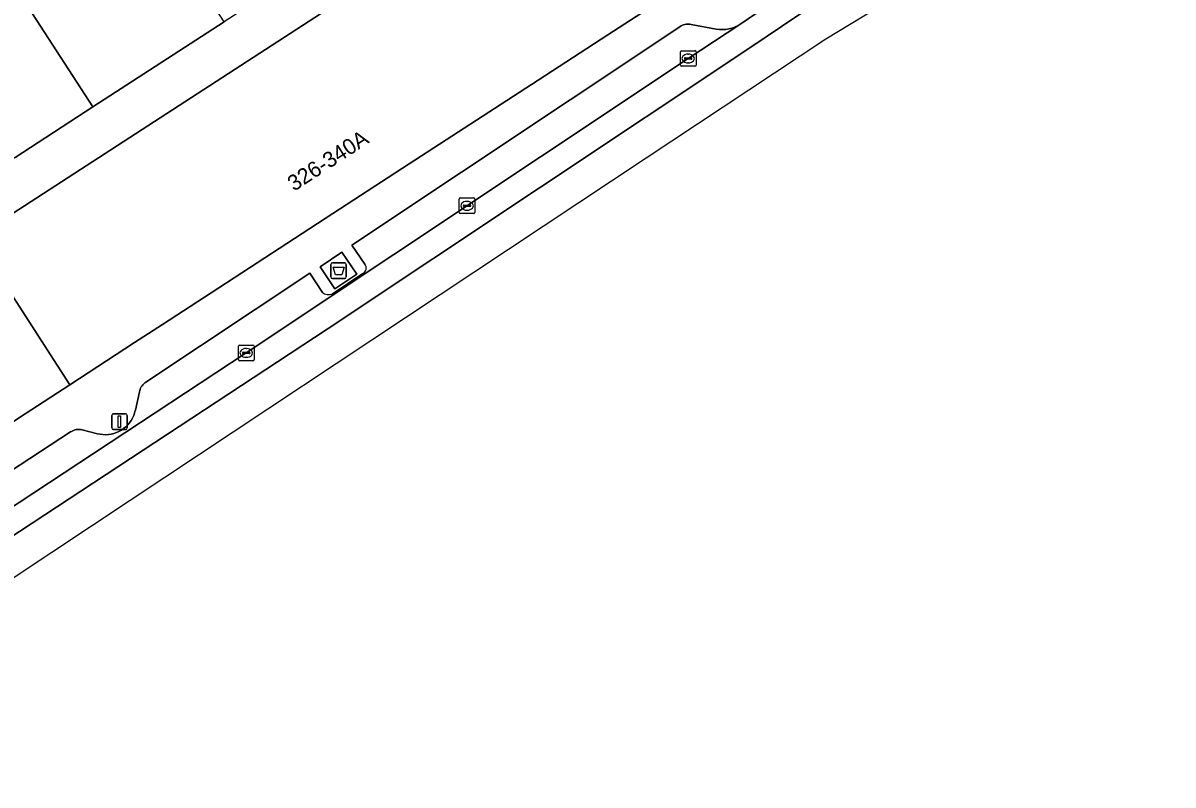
# Model space of a CAD drawing. Extents: x 159217 to 160349, y 381246 to 382172.
# Drawn here: x 160088.8 to 160162.3, y 381567.9 to 381616.5 of the extents above; entities that cross this region are included whole.
import ezdxf

# ---------------------------------------------------------------- set-up
doc = ezdxf.new("R2010")
doc.units = 0
for name, color, linetype in [('IMGEO_Afval_apart_plaats', 7, 'Continuous'), ('IMGEO_Erf', 7, 'Continuous'), ('IMGEO_Kolk', 7, 'Continuous'), ('IMGEO_Lichtmast', 7, 'Continuous'), ('IMGEO_Pand', 7, 'Continuous'), ('IMGEO_Pand_nummerreeks', 7, 'Continuous'), ('IMGEO_Parkeervlak_open', 7, 'Continuous'), ('IMGEO_Rijbaan_lokaal_gesloten', 7, 'Continuous'), ('IMGEO_Rijbaan_lokaal_open', 7, 'Continuous'), ('IMGEO_Voetpad_gesloten', 7, 'Continuous'), ('IMGEO_Voetpad_open', 7, 'Continuous')]:
    doc.layers.add(name, color=color, linetype=linetype)

msp = doc.modelspace()

# ---------------------------------------------------------------- linework, layer by layer
at = {"layer": 'IMGEO_Afval_apart_plaats'}
for p, q in [((160108.477, 381600.312), (160108.477, 381601.112)), ((160108.477, 381601.112), (160108.477, 381600.312)), ((160108.577, 381601.212), (160109.367, 381601.212)), ((160109.367, 381601.212), (160108.577, 381601.212)), ((160109.467, 381601.112), (160109.467, 381600.312)), ((160109.467, 381600.312), (160109.467, 381601.112)), ((160109.367, 381600.212), (160108.577, 381600.212)), ((160108.577, 381600.212), (160109.367, 381600.212))]:
    msp.add_line(p, q, dxfattribs=at)
msp.add_lwpolyline([(160108.62, 381600.926), (160109.324, 381600.926), (160109.175, 381600.456), (160108.769, 381600.456), (160108.62, 381600.926)], dxfattribs=at)
for centre, start, end in [((160108.577, 381601.112), 90, 180), ((160108.577, 381601.112), 90, 180), ((160109.367, 381601.112), 0, 90), ((160109.367, 381601.112), 360, 90), ((160108.577, 381600.312), 180, 270), ((160108.577, 381600.312), 180, 270), ((160109.367, 381600.312), 270, 0), ((160109.367, 381600.312), 270, 0)]:
    msp.add_arc(centre, 0.1, start, end, dxfattribs=at)
at = {"layer": 'IMGEO_Erf'}
msp.add_lwpolyline([(160085.755, 381602.808), (160117.326, 381623.315), (160116.481, 381624.633), (160114.624, 381625), (160101.666, 381616.599), (160093.287, 381611.166), (160088.317, 381607.943), (160084.116, 381605.216), (160082.22, 381607.999), (160077.994, 381605.329), (160073.61, 381602.559), (160076.424, 381598.203), (160080.811, 381601.187), (160084.945, 381603.999)], close=True, dxfattribs=at)
at = {"layer": 'IMGEO_Kolk'}
for p, q in [((160130.8, 381613.837), (160130.8, 381614.689)), ((160130.875, 381614.763), (160131.727, 381614.763)), ((160131.059, 381614.257), (160131.059, 381614.269)), ((160131.102, 381614.306), (160131.5, 381614.306)), ((160131.288, 381614.543), (160131.313, 381614.543)), ((160131.543, 381614.269), (160131.543, 381614.257)), ((160131.801, 381614.689), (160131.801, 381613.837)), ((160131.727, 381613.763), (160130.875, 381613.763)), ((160131.497, 381614.22), (160131.099, 381614.22)), ((160131.311, 381613.983), (160131.286, 381613.983)), ((160116.68, 381604.43), (160116.68, 381605.282)), ((160116.755, 381605.356), (160117.607, 381605.356)), ((160116.939, 381604.85), (160116.939, 381604.862)), ((160117.377, 381604.813), (160116.979, 381604.813)), ((160116.982, 381604.899), (160117.38, 381604.899)), ((160117.168, 381605.136), (160117.193, 381605.136)), ((160117.423, 381604.862), (160117.423, 381604.85)), ((160117.681, 381605.282), (160117.681, 381604.43)), ((160117.607, 381604.356), (160116.755, 381604.356)), ((160117.191, 381604.576), (160117.166, 381604.576)), ((160102.576, 381595.035), (160102.576, 381595.887)), ((160102.651, 381595.961), (160103.503, 381595.961)), ((160103.577, 381595.887), (160103.577, 381595.035)), ((160102.835, 381595.455), (160102.835, 381595.467)), ((160103.273, 381595.418), (160102.875, 381595.418)), ((160102.878, 381595.504), (160103.276, 381595.504)), ((160103.087, 381595.181), (160103.062, 381595.181)), ((160103.064, 381595.741), (160103.089, 381595.741)), ((160103.319, 381595.467), (160103.319, 381595.455)), ((160103.503, 381594.961), (160102.651, 381594.961))]:
    msp.add_line(p, q, dxfattribs=at)
for points in [[(160130.8, 381613.837), (160130.8, 381614.689)], [(160130.875, 381614.763), (160131.727, 381614.763)], [(160131.801, 381614.689), (160131.801, 381613.837)], [(160131.727, 381613.763), (160130.875, 381613.763)], [(160116.68, 381604.43), (160116.68, 381605.282)], [(160116.755, 381605.356), (160117.607, 381605.356)], [(160117.681, 381605.282), (160117.681, 381604.43)], [(160117.607, 381604.356), (160116.755, 381604.356)], [(160102.576, 381595.035), (160102.576, 381595.887)], [(160102.651, 381595.961), (160103.503, 381595.961)], [(160103.577, 381595.887), (160103.577, 381595.035)], [(160103.503, 381594.961), (160102.651, 381594.961)]]:
    msp.add_lwpolyline(points, dxfattribs=at)
for centre, radius, start, end in [((160130.877, 381614.687), 0.0765, 91.55205, 178.44795), ((160130.877, 381614.687), 0.0765, 91.55205, 178.44795), ((160131.099, 381614.266), 0.0403, 85.87752, 175.75265), ((160131.096, 381614.256), 0.0366, 178.93798, 274.71019), ((160131.5, 381614.263), 0.043, 264.86636, 352.45326), ((160131.504, 381614.268), 0.0386, 1.73085, 96.63898), ((160131.725, 381614.687), 0.0765, 1.55205, 88.44795), ((160131.725, 381614.687), 0.0765, 1.55205, 88.44795), ((160130.877, 381613.839), 0.0765, 181.55205, 268.44795), ((160130.877, 381613.839), 0.0765, 181.55205, 268.44795), ((160131.725, 381613.839), 0.0765, 271.55205, 358.44795), ((160131.725, 381613.839), 0.0765, 271.55205, 358.44795), ((160116.757, 381605.28), 0.0765, 91.55205, 178.44795), ((160116.757, 381605.28), 0.0765, 91.55205, 178.44795), ((160116.979, 381604.859), 0.0403, 85.87752, 175.75265), ((160116.976, 381604.849), 0.0366, 178.93798, 274.71019), ((160117.38, 381604.856), 0.043, 264.86636, 352.45326), ((160117.384, 381604.861), 0.0386, 1.73085, 96.63898), ((160117.605, 381605.28), 0.0765, 1.55205, 88.44795), ((160117.605, 381605.28), 0.0765, 1.55205, 88.44795), ((160116.757, 381604.432), 0.0765, 181.55205, 268.44795), ((160116.757, 381604.432), 0.0765, 181.55205, 268.44795), ((160117.605, 381604.432), 0.0765, 271.55205, 358.44795), ((160117.605, 381604.432), 0.0765, 271.55205, 358.44795), ((160102.653, 381595.885), 0.0765, 91.55205, 178.44795), ((160102.653, 381595.885), 0.0765, 91.55205, 178.44795), ((160103.501, 381595.885), 0.0765, 1.55205, 88.44795), ((160103.501, 381595.885), 0.0765, 1.55205, 88.44795), ((160102.875, 381595.464), 0.0403, 85.87752, 175.75265), ((160102.872, 381595.454), 0.0366, 178.93798, 274.71019), ((160103.276, 381595.461), 0.043, 264.86636, 352.45326), ((160103.28, 381595.466), 0.0386, 1.73085, 96.63898), ((160102.653, 381595.037), 0.0765, 181.55205, 268.44795), ((160102.653, 381595.037), 0.0765, 181.55205, 268.44795), ((160103.501, 381595.037), 0.0765, 271.55205, 358.44795), ((160103.501, 381595.037), 0.0765, 271.55205, 358.44795)]:
    msp.add_arc(centre, radius, start, end, dxfattribs=at)
for centre, major_axis, ratio, start_param, end_param in [((160131.287, 381614.263), (-0.387, 0.002), 0.722429, 4.712389, 7.853982), ((160131.312, 381614.263), (-0.39, 0.002), 0.717154, 1.570796, 4.712389), ((160117.167, 381604.856), (-0.387, 0.002), 0.722429, 4.712389, 7.853982), ((160117.192, 381604.856), (-0.39, 0.002), 0.717154, 1.570796, 4.712389), ((160103.063, 381595.461), (-0.387, 0.002), 0.722429, 4.712389, 7.853982), ((160103.088, 381595.461), (-0.39, 0.002), 0.717154, 1.570796, 4.712389)]:
    msp.add_ellipse(centre, major_axis=major_axis, ratio=ratio, start_param=start_param, end_param=end_param, dxfattribs=at)
at = {"layer": 'IMGEO_Lichtmast'}
for p, q in [((160094.587, 381591.567), (160095.377, 381591.567)), ((160095.377, 381591.567), (160094.587, 381591.567)), ((160094.487, 381590.667), (160094.487, 381591.467)), ((160094.487, 381591.467), (160094.487, 381590.667)), ((160095.477, 381591.467), (160095.477, 381590.667)), ((160095.477, 381590.667), (160095.477, 381591.467)), ((160095.377, 381590.567), (160094.587, 381590.567)), ((160094.587, 381590.567), (160095.377, 381590.567))]:
    msp.add_line(p, q, dxfattribs=at)
msp.add_lwpolyline([(160094.907, 381591.442), (160095.057, 381591.442), (160095.057, 381590.692), (160094.907, 381590.692), (160094.907, 381591.442)], dxfattribs=at)
for centre, start, end in [((160094.587, 381591.467), 90, 180), ((160094.587, 381591.467), 90, 180), ((160095.377, 381591.467), 0, 90), ((160095.377, 381591.467), 360, 90), ((160094.587, 381590.667), 180, 270), ((160094.587, 381590.667), 180, 270), ((160095.377, 381590.667), 270, 0), ((160095.377, 381590.667), 270, 0)]:
    msp.add_arc(centre, 0.1, start, end, dxfattribs=at)
at = {"layer": 'IMGEO_Pand'}
msp.add_lwpolyline([(160117.326, 381623.315), (160085.755, 381602.808), (160091.81, 381593.432), (160095.951, 381596.125), (160097.719, 381597.275), (160099.06, 381598.147), (160100.827, 381599.296), (160108.609, 381604.357), (160110.378, 381605.507), (160111.719, 381606.379), (160113.487, 381607.529), (160121.301, 381612.611), (160123.062, 381613.756), (160124.411, 381614.634), (160126.18, 381615.784), (160130.515, 381618.603)], dxfattribs=at)
msp.add_lwpolyline([(160085.755, 381602.808), (160084.945, 381603.999), (160080.811, 381601.187), (160076.424, 381598.203), (160073.61, 381602.559), (160077.994, 381605.329), (160082.22, 381607.999), (160078.905, 381612.867), (160074.71, 381610.148), (160066.385, 381604.751), (160070.382, 381598.632), (160072.253, 381595.767), (160073.116, 381594.445), (160074.124, 381593.909), (160079.028, 381586.399), (160080.507, 381586.051), (160080.717, 381586.188), (160081.847, 381586.926), (160083.94, 381588.293), (160086.871, 381590.207), (160088.964, 381591.573), (160091.81, 381593.432)], close=True, dxfattribs=at)
at = {"layer": 'IMGEO_Parkeervlak_open'}
msp.add_lwpolyline([(160101.666, 381616.599), (160088.785, 381636.465), (160080.393, 381631.009), (160093.287, 381611.166)], close=True, dxfattribs=at)
for points in [[(160131.492, 381616.441), (160131.412, 381616.454), (160131.331, 381616.461), (160131.249, 381616.459), (160131.168, 381616.451), (160131.088, 381616.435), (160131.01, 381616.413), (160130.934, 381616.383), (160130.862, 381616.347), (160130.792, 381616.305), (160130.759, 381616.281)], [(160133.091, 381616.134), (160131.492, 381616.441)], [(160070.937, 381574.339), (160087.579, 381585.252), (160103.074, 381595.46), (160131.298, 381614.262), (160134.606, 381616.433)], [(160130.759, 381616.281), (160109.83, 381602.351)], [(160134.606, 381616.433), (160134.484, 381616.365), (160134.298, 381616.279), (160134.105, 381616.21), (160133.906, 381616.159), (160133.704, 381616.125), (160133.5, 381616.11), (160133.295, 381616.113), (160133.091, 381616.134)], [(160109.83, 381602.351), (160110.656, 381601.137)], [(160107.143, 381600.562), (160096.675, 381593.595)], [(160107.947, 381599.327), (160107.143, 381600.562)], [(160110.517, 381600.522), (160108.562, 381599.219)], [(160096.253, 381592.971), (160095.998, 381591.809)], [(160096.675, 381593.595), (160096.605, 381593.545), (160096.539, 381593.488), (160096.479, 381593.426), (160096.424, 381593.359), (160096.376, 381593.287), (160096.334, 381593.211), (160096.299, 381593.132), (160096.272, 381593.05), (160096.253, 381592.971)], [(160095.998, 381591.809), (160095.994, 381591.792), (160095.949, 381591.621), (160095.889, 381591.455), (160095.815, 381591.295), (160095.726, 381591.143), (160095.624, 381590.999), (160095.51, 381590.864), (160095.384, 381590.741), (160095.248, 381590.629), (160095.102, 381590.53), (160094.948, 381590.444), (160094.786, 381590.372), (160094.619, 381590.315), (160094.448, 381590.273), (160094.273, 381590.247), (160094.097, 381590.236), (160093.921, 381590.241), (160093.746, 381590.262), (160093.573, 381590.298)], [(160091.857, 381590.422), (160082.741, 381584.465)], [(160092.596, 381590.558), (160092.503, 381590.571), (160092.409, 381590.575), (160092.314, 381590.572), (160092.221, 381590.559), (160092.129, 381590.539), (160092.039, 381590.51), (160091.952, 381590.473), (160091.869, 381590.429), (160091.857, 381590.422)], [(160093.573, 381590.298), (160092.596, 381590.558)]]:
    msp.add_lwpolyline(points, dxfattribs=at)
for centre, radius, start, end in [((160110.326, 381600.888), 0.413, 297.51748, 37.01094), ((160108.347, 381599.801), 0.621, 229.83387, 290.24585)]:
    msp.add_arc(centre, radius, start, end, dxfattribs=at)
at = {"layer": 'IMGEO_Rijbaan_lokaal_gesloten'}
for points in [[(160068.226, 381567.865), (160095.673, 381586.064), (160128.623, 381607.912), (160140.09, 381615.515), (160156.598, 381625.529), (160171.421, 381635.297), (160187.922, 381660.808), (160192.653, 381669.888), (160214.799, 381712.395)], [(160195.4, 381675.172), (160192.483, 381669.642), (160190.409, 381665.724), (160188.106, 381661.73), (160185.188, 381657.275), (160182.04, 381652.59), (160178.585, 381647.981), (160174.132, 381642.912), (160167.068, 381636.152), (160166.394, 381635.674), (160165.31, 381637.041), (160161.833, 381634.337), (160160.845, 381633.624), (160160.612, 381633.458), (160160.414, 381633.335), (160138.741, 381619.241), (160139.591, 381617.866), (160137.265, 381616.308), (160135.358, 381615.03), (160108.254, 381596.98), (160074.47, 381574.782)], [(160074.47, 381574.782), (160108.254, 381596.98), (160135.358, 381615.03), (160137.265, 381616.308), (160139.591, 381617.866), (160138.741, 381619.241), (160137.64, 381618.525), (160136.26, 381617.573), (160134.606, 381616.433), (160131.298, 381614.262), (160103.074, 381595.46), (160087.579, 381585.252)]]:
    msp.add_lwpolyline(points, dxfattribs=at)
at = {"layer": 'IMGEO_Rijbaan_lokaal_open'}
msp.add_lwpolyline([(160088.317, 381607.943), (160093.287, 381611.166), (160080.393, 381631.009)], dxfattribs=at)
at = {"layer": 'IMGEO_Voetpad_gesloten'}
msp.add_lwpolyline([(160109.186, 381601.898), (160107.793, 381600.962), (160108.741, 381599.551), (160110.134, 381600.487)], close=True, dxfattribs=at)
at = {"layer": 'IMGEO_Voetpad_open'}
for points in [[(160138.761, 381619.585), (160136.847, 381622.746), (160136.333, 381622.402), (160134.154, 381620.946), (160133.751, 381620.687), (160133.566, 381620.568), (160130.515, 381618.603), (160126.18, 381615.784), (160124.411, 381614.634), (160123.062, 381613.756), (160121.301, 381612.611), (160113.487, 381607.529), (160111.719, 381606.379), (160110.378, 381605.507), (160108.609, 381604.357), (160100.827, 381599.296), (160099.06, 381598.147), (160097.719, 381597.275), (160095.951, 381596.125), (160091.81, 381593.432), (160088.964, 381591.573), (160086.871, 381590.207)], [(160110.656, 381601.137), (160109.83, 381602.351), (160130.759, 381616.281), (160130.792, 381616.305), (160130.862, 381616.347), (160130.934, 381616.383), (160131.01, 381616.413), (160131.088, 381616.435), (160131.168, 381616.451), (160131.249, 381616.459), (160131.331, 381616.461), (160131.412, 381616.454), (160131.492, 381616.441), (160133.091, 381616.134), (160133.295, 381616.113), (160133.5, 381616.11), (160133.704, 381616.125), (160133.906, 381616.159), (160134.105, 381616.21), (160134.298, 381616.279), (160134.484, 381616.365), (160134.606, 381616.433), (160136.26, 381617.573), (160137.64, 381618.525)], [(160082.741, 381584.465), (160091.857, 381590.422), (160091.869, 381590.429), (160091.952, 381590.473), (160092.039, 381590.51), (160092.129, 381590.539), (160092.221, 381590.559), (160092.314, 381590.572), (160092.409, 381590.575), (160092.503, 381590.571), (160092.596, 381590.558), (160093.573, 381590.298), (160093.746, 381590.262), (160093.921, 381590.241), (160094.097, 381590.236), (160094.273, 381590.247), (160094.448, 381590.273), (160094.619, 381590.315), (160094.786, 381590.372), (160094.948, 381590.444), (160095.102, 381590.53), (160095.248, 381590.629), (160095.384, 381590.741), (160095.51, 381590.864), (160095.624, 381590.999), (160095.726, 381591.143), (160095.815, 381591.295), (160095.889, 381591.455), (160095.949, 381591.621), (160095.994, 381591.792), (160095.998, 381591.809), (160096.253, 381592.971), (160096.272, 381593.05), (160096.299, 381593.132), (160096.334, 381593.211), (160096.376, 381593.287), (160096.424, 381593.359), (160096.479, 381593.426), (160096.539, 381593.488), (160096.605, 381593.545), (160096.675, 381593.595), (160107.143, 381600.562), (160107.947, 381599.327)], [(160108.562, 381599.219), (160110.517, 381600.522)]]:
    msp.add_lwpolyline(points, dxfattribs=at)
msp.add_lwpolyline([(160109.186, 381601.898), (160110.134, 381600.487), (160108.741, 381599.551), (160107.793, 381600.962)], close=True, dxfattribs=at)
for centre, radius, start, end in [((160110.326, 381600.888), 0.413, 297.51748, 37.01094), ((160108.347, 381599.801), 0.621, 229.83387, 290.24585)]:
    msp.add_arc(centre, radius, start, end, dxfattribs=at)

# ---------------------------------------------------------------- texts
at = {"layer": 'IMGEO_Pand_nummerreeks'}
msp.add_text('326-340A', height=1, rotation=33.03713, dxfattribs=at).set_placement((160106.13, 381605.751))

doc.saveas('drawing.dxf')
